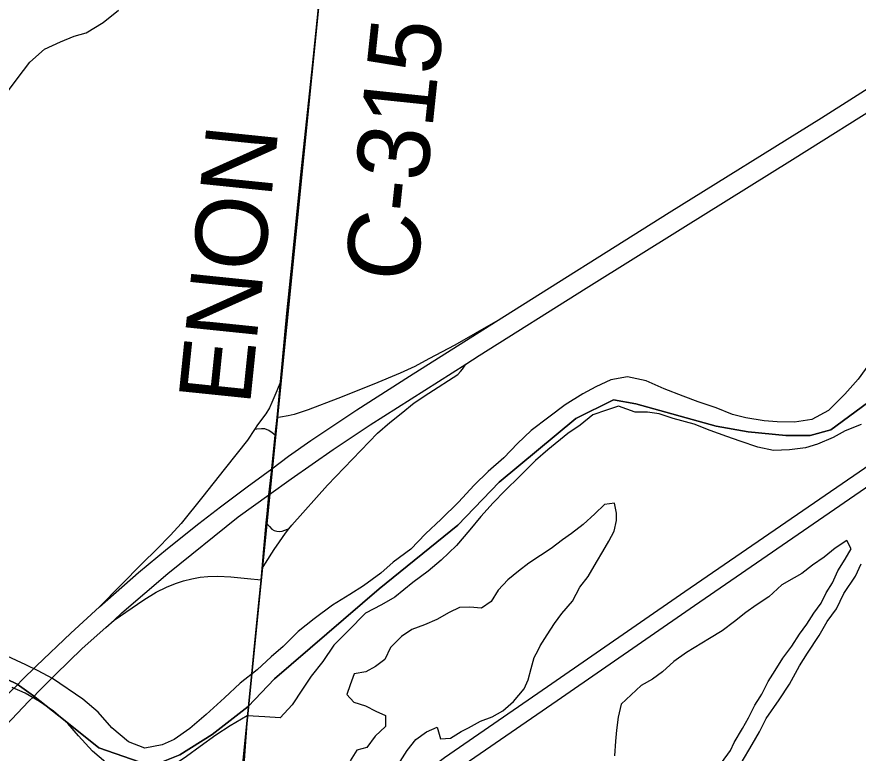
# Model space of a CAD drawing. Extents: x 831 to 1552, y 430 to 870.
# Drawn here: x 1320.48 to 1333.77, y 687.8 to 699.44 of the extents above; entities that cross this region are included whole.
import ezdxf

# ---------------------------------------------------------------- set-up
doc = ezdxf.new("R2010")
doc.units = 0
for name, color, linetype in [('GM_X_Corporation', 7, 'Continuous'), ('GM_X_County_Road', 7, 'Continuous'), ('GM_X_County_Road_Text', 7, 'Continuous'), ('GM_X_Interchange_Ramps', 7, 'Continuous'), ('GM_X_Major_River', 7, 'Continuous'), ('GM_X_Minor_Lake', 7, 'Continuous'), ('GM_X_Minor_River', 7, 'Continuous'), ('GM_X_Rail_Line', 7, 'Continuous'), ('GM_X_State_Route', 7, 'Continuous')]:
    doc.layers.add(name, color=color, linetype=linetype)

msp = doc.modelspace()

# ---------------------------------------------------------------- linework, layer by layer
at = {"layer": 'GM_X_Corporation'}
for points in [[(1305.299, 704.746), (1325.539, 702.531), (1323.531, 682.478), (1303.37, 684.858)], [(1325.539, 702.531), (1346.049, 700.645), (1343.776, 680.603), (1323.531, 682.478)]]:
    msp.add_lwpolyline(points, close=True, dxfattribs=at)
for points in [[(1334.014, 693.412), (1333.334, 692.909), (1333.008, 692.82), (1332.624, 692.82), (1332.032, 692.88), (1331.526, 692.968), (1330.257, 693.324), (1329.902, 693.384), (1329.31, 693.088), (1328.097, 692.083), (1327.445, 691.402), (1326.203, 690.397), (1324.546, 688.978), (1324.133, 688.539), (1323.561, 688.096), (1323.054, 687.776), (1322.788, 687.67), (1322.547, 687.616), (1321.774, 687.883), (1321.239, 688.312), (1320.74, 688.708), (1320.481, 688.893), (1319.693, 689.271)], [(1319.693, 689.271), (1320.481, 688.893), (1320.74, 688.708), (1321.239, 688.312), (1321.774, 687.883), (1322.547, 687.616), (1322.788, 687.67), (1323.054, 687.776), (1323.561, 688.096), (1324.133, 688.539), (1324.546, 688.978), (1326.203, 690.397), (1327.445, 691.402), (1328.097, 692.083), (1329.31, 693.088), (1329.902, 693.384), (1330.257, 693.324), (1331.526, 692.968), (1332.032, 692.88), (1332.624, 692.82), (1333.008, 692.82), (1333.334, 692.909), (1334.014, 693.412)]]:
    msp.add_lwpolyline(points, dxfattribs=at)
at = {"layer": 'GM_X_County_Road'}
msp.add_line((1324.335, 690.542), (1324.351, 690.717), dxfattribs=at)
for points in [[(1324.84, 695.684), (1324.961, 696.895), (1325.148, 698.665), (1325.236, 699.531), (1325.278, 699.986), (1325.311, 700.327), (1325.389, 701.047), (1325.475, 701.908), (1325.527, 702.402), (1325.544, 702.539)], [(1324.645, 693.667), (1324.745, 694.753), (1324.828, 695.565), (1324.84, 695.684)], [(1324.561, 692.828), (1324.59, 693.105), (1324.619, 693.387), (1324.645, 693.667)], [(1324.417, 691.439), (1324.43, 691.585), (1324.461, 691.886), (1324.505, 692.296), (1324.539, 692.617), (1324.561, 692.828)], [(1324.351, 690.717), (1324.381, 691.031), (1324.417, 691.439)], [(1324.3, 690.18), (1324.325, 690.435), (1324.335, 690.542)], [(1323.917, 686.075), (1323.927, 686.185), (1323.929, 686.202), (1323.992, 686.811), (1324.07, 687.616), (1324.127, 688.42), (1324.137, 688.528), (1324.14, 688.555), (1324.234, 689.495), (1324.3, 690.18)]]:
    msp.add_lwpolyline(points, dxfattribs=at)
at = {"layer": 'GM_X_Interchange_Ramps'}
for points in [[(1328.041, 694.617), (1327.397, 694.25), (1326.985, 694.031), (1326.763, 693.914), (1326.535, 693.809), (1326.119, 693.634), (1325.547, 693.408), (1325.079, 693.227), (1324.857, 693.152), (1324.764, 693.131), (1324.643, 693.113), (1324.59, 693.105)], [(1324.351, 690.717), (1324.405, 690.802), (1324.543, 691.019), (1324.627, 691.141), (1324.723, 691.279), (1324.777, 691.346), (1324.821, 691.402), (1325.385, 692.035), (1326.177, 692.858), (1326.371, 693.028), (1326.547, 693.17), (1326.752, 693.337), (1326.984, 693.493), (1327.442, 693.788), (1327.485, 693.831), (1327.516, 693.87), (1327.572, 693.951)], [(1324.645, 693.667), (1324.586, 693.528), (1324.507, 693.341), (1324.468, 693.26), (1324.409, 693.164), (1324.281, 692.988), (1324.232, 692.914), (1324.12, 692.745), (1323.96, 692.543), (1323.754, 692.285), (1323.418, 691.859), (1323.072, 691.428), (1322.905, 691.245), (1322.689, 691.023), (1322.459, 690.796), (1321.785, 690.116)], [(1324.561, 692.828), (1324.512, 692.863), (1324.458, 692.901), (1324.396, 692.925), (1324.342, 692.929), (1324.268, 692.919), (1324.232, 692.914)], [(1324.417, 691.439), (1324.469, 691.383), (1324.507, 691.343), (1324.543, 691.32), (1324.587, 691.309), (1324.628, 691.305), (1324.67, 691.312), (1324.755, 691.339), (1324.777, 691.346)], [(1322.015, 689.904), (1322.483, 690.223), (1322.679, 690.343), (1322.842, 690.427), (1322.983, 690.485), (1323.108, 690.526), (1323.242, 690.558), (1323.374, 690.582), (1323.496, 690.595), (1323.652, 690.6), (1323.86, 690.589), (1324.124, 690.563), (1324.335, 690.542)]]:
    msp.add_lwpolyline(points, dxfattribs=at)
at = {"layer": 'GM_X_Major_River'}
for points in [[(1333.946, 693.957), (1333.766, 693.71), (1333.555, 693.472), (1333.298, 693.219), (1333.036, 693.072), (1332.762, 693.033), (1332.488, 693.039), (1332.283, 693.051), (1331.995, 693.103), (1331.783, 693.154), (1331.527, 693.258), (1331.24, 693.356), (1331.006, 693.445), (1330.704, 693.558), (1330.418, 693.686), (1330.123, 693.746), (1329.863, 693.699), (1329.625, 693.59), (1329.417, 693.48), (1329.139, 693.304), (1328.884, 693.112), (1328.605, 692.898), (1328.388, 692.697), (1328.17, 692.466), (1327.921, 692.251), (1327.703, 692.035), (1327.454, 691.767), (1327.182, 691.499), (1326.933, 691.269), (1326.699, 691.024), (1326.421, 690.817), (1326.227, 690.646), (1325.956, 690.447), (1325.74, 690.307), (1325.462, 690.139), (1325.176, 689.924), (1324.921, 689.725), (1324.687, 689.487), (1324.493, 689.324), (1324.275, 689.116), (1324.004, 688.909), (1323.756, 688.678), (1323.468, 688.411), (1323.212, 688.189), (1322.965, 688.019)], [(1333.818, 692.994), (1333.565, 692.893), (1333.372, 692.791), (1333.127, 692.683), (1332.935, 692.626), (1332.683, 692.594), (1332.432, 692.584), (1332.182, 692.635), (1331.903, 692.733), (1331.692, 692.806), (1331.428, 692.903), (1331.179, 693), (1330.846, 693.091), (1330.627, 693.164), (1330.438, 693.191), (1330.247, 693.188), (1329.983, 693.285), (1329.792, 693.221), (1329.577, 693.15), (1329.376, 692.987), (1329.182, 692.854), (1328.865, 692.595), (1328.671, 692.425), (1328.422, 692.179), (1328.188, 691.949), (1328.001, 691.755), (1327.806, 691.539), (1327.634, 691.33), (1327.423, 691.083), (1327.182, 690.853), (1326.973, 690.675), (1326.733, 690.498), (1326.447, 690.269), (1326.238, 690.144), (1325.984, 690.013), (1325.712, 689.737), (1325.486, 689.507), (1325.313, 689.252), (1325.125, 689.02), (1324.991, 688.81), (1324.826, 688.563), (1324.639, 688.362), (1324.396, 688.375)], [(1322.965, 688.019), (1322.773, 687.932), (1322.498, 687.878), (1322.242, 687.982), (1321.98, 688.201), (1321.765, 688.449), (1321.519, 688.653), (1321.039, 688.983), (1320.814, 689.102), (1320.618, 689.198), (1320.325, 689.334)], [(1324.396, 688.375), (1324.115, 688.389), (1323.845, 688.235), (1323.621, 688.088), (1323.373, 687.904), (1323.157, 687.749), (1322.91, 687.579), (1322.641, 687.494), (1322.405, 687.484), (1322.155, 687.528), (1321.884, 687.656), (1321.675, 687.835), (1321.453, 688.076), (1321.282, 688.27), (1321.058, 688.465), (1320.833, 688.615), (1320.608, 688.749), (1320.405, 688.838)]]:
    msp.add_lwpolyline(points, dxfattribs=at)
at = {"layer": 'GM_X_Minor_Lake'}
for points in [[(1328.711, 689.429), (1328.746, 689.496), (1328.854, 689.669), (1328.97, 689.85), (1329.086, 690.008), (1329.256, 690.203), (1329.372, 690.422), (1329.504, 690.595), (1329.636, 690.822), (1329.736, 690.987), (1329.83, 691.153), (1329.915, 691.312), (1329.948, 691.478), (1329.949, 691.592), (1329.921, 691.752), (1329.761, 691.731), (1329.607, 691.581), (1329.423, 691.416), (1329.238, 691.274), (1329.1, 691.17), (1328.916, 691.035), (1328.748, 690.923), (1328.564, 690.804), (1328.403, 690.677), (1328.234, 690.542), (1328.08, 690.377), (1327.972, 690.196), (1327.818, 690.092), (1327.636, 690.109), (1327.469, 690.104), (1327.309, 690.022), (1327.11, 689.911), (1326.919, 689.83), (1326.72, 689.756), (1326.552, 689.644), (1326.382, 689.472), (1326.289, 689.283), (1326.143, 689.171), (1325.99, 689.089), (1325.807, 689.054)], [(1332.22, 688.69), (1332.246, 688.732), (1332.347, 688.935), (1332.456, 689.109), (1332.58, 689.305), (1332.719, 689.493), (1332.843, 689.681), (1332.959, 689.839), (1333.067, 690.013), (1333.183, 690.171), (1333.261, 690.337), (1333.362, 690.495), (1333.448, 690.684), (1333.564, 690.865), (1333.657, 691.031), (1333.59, 691.161), (1333.407, 691.041), (1333.23, 690.899), (1333.046, 690.772), (1332.877, 690.638), (1332.755, 690.571), (1332.564, 690.459), (1332.356, 690.272), (1332.157, 690.138), (1331.996, 690.026), (1331.812, 689.884), (1331.62, 689.734), (1331.421, 689.615), (1331.054, 689.392), (1330.855, 689.25), (1330.678, 689.085), (1330.517, 688.973), (1330.341, 688.869), (1330.026, 688.577)], [(1326.535, 687.67), (1326.643, 687.844), (1326.782, 688.016), (1326.951, 688.136), (1327.119, 688.21), (1327.17, 688.027), (1327.33, 688.04), (1327.498, 688.144), (1327.613, 688.204), (1327.804, 688.308), (1327.987, 688.374), (1328.156, 688.47), (1328.324, 688.62), (1328.494, 688.816), (1328.557, 688.959), (1328.604, 689.141), (1328.652, 689.315), (1328.711, 689.429)], [(1325.807, 689.054), (1325.744, 688.88), (1325.689, 688.729), (1325.802, 688.606), (1325.984, 688.55), (1326.15, 688.465), (1326.301, 688.394), (1326.299, 688.22), (1326.137, 688.07), (1326.006, 687.889), (1325.846, 687.846), (1325.745, 687.68)], [(1331.61, 687.646), (1331.749, 687.842), (1331.811, 687.97), (1331.943, 688.189), (1332.036, 688.362), (1332.138, 688.558), (1332.22, 688.69)], [(1330.026, 688.577), (1329.978, 688.372), (1329.952, 688.167), (1329.935, 687.993), (1329.917, 687.758)]]:
    msp.add_lwpolyline(points, dxfattribs=at)
at = {"layer": 'GM_X_Minor_River'}
for points in [[(1320.314, 698.234), (1320.483, 698.459), (1320.684, 698.723), (1320.915, 698.925), (1321.167, 699.043), (1321.381, 699.132), (1321.571, 699.183), (1321.839, 699.346), (1322.085, 699.541)], [(1331.921, 687.642), (1332.092, 687.936), (1332.209, 688.14), (1332.317, 688.351), (1332.519, 688.645), (1332.681, 688.893), (1332.844, 689.18), (1332.968, 689.384), (1333.154, 689.662), (1333.278, 689.881), (1333.425, 690.084), (1333.542, 690.326), (1333.728, 690.597), (1333.814, 690.793)]]:
    msp.add_lwpolyline(points, dxfattribs=at)
at = {"layer": 'GM_X_Rail_Line'}
for points in [[(1324.617, 685.605), (1327.389, 687.515), (1329.015, 688.636), (1331.181, 690.137), (1334.291, 692.272), (1336.956, 694.104), (1342.764, 698.096), (1344.19, 698.989), (1345.244, 699.602), (1346.087, 700.054), (1346.951, 700.47), (1347.965, 700.91), (1350.503, 701.962), (1353.086, 703.026), (1355.423, 703.992), (1360.057, 705.898)], [(1324.617, 685.605), (1325.172, 686.041), (1325.529, 686.336), (1326.385, 687.077), (1326.953, 687.524), (1327.234, 687.732), (1328.862, 688.855), (1331.029, 690.356), (1334.139, 692.492)]]:
    msp.add_lwpolyline(points, dxfattribs=at)
at = {"layer": 'GM_X_State_Route'}
for points in [[(1327.572, 693.951), (1327.781, 694.084), (1329.474, 695.148), (1330.997, 696.104), (1332.731, 697.181), (1334.273, 698.15), (1336.026, 699.258), (1337.813, 700.381), (1339.619, 701.524), (1340.853, 702.296), (1342.496, 703.341), (1344.305, 704.48), (1346.259, 705.713), (1348.062, 706.849), (1349.964, 708.043), (1351.69, 709.137), (1352.765, 709.811)], [(1321.785, 690.116), (1322.402, 690.657), (1322.856, 691.036), (1323.351, 691.43), (1323.695, 691.693), (1324.118, 692.012), (1324.37, 692.194), (1324.505, 692.296), (1324.767, 692.494), (1325.122, 692.743), (1325.846, 693.225), (1326.683, 693.761), (1328.041, 694.617), (1330.783, 696.344), (1333.187, 697.843), (1335.988, 699.621)], [(1322.015, 689.904), (1322.135, 690.017), (1322.865, 690.642), (1323.973, 691.534), (1324.461, 691.886), (1324.812, 692.138), (1325.476, 692.602), (1326.061, 692.989), (1327.572, 693.951)], [(1316.766, 684.819), (1317.703, 685.861), (1318.328, 686.553), (1319.452, 687.797), (1319.959, 688.343), (1320.391, 688.789), (1320.486, 688.883), (1320.559, 688.955), (1320.789, 689.182), (1321.328, 689.696), (1321.785, 690.116)], [(1316.972, 684.576), (1316.999, 684.606), (1318.606, 686.397), (1319.425, 687.306), (1320.209, 688.142), (1320.669, 688.622), (1320.744, 688.697), (1320.82, 688.773), (1321.091, 689.044), (1321.508, 689.455), (1321.884, 689.788), (1322.015, 689.904)]]:
    msp.add_lwpolyline(points, dxfattribs=at)

# ---------------------------------------------------------------- texts
at = {"layer": 'GM_X_County_Road_Text'}
for s, rotation, p in [('C-315', 84.0018, (1326.785, 695.222)), ('ENON', 84.1186, (1324.159, 693.282))]:
    msp.add_text(s, height=1.1364, rotation=rotation, dxfattribs=at).set_placement(p)

doc.saveas('drawing.dxf')
